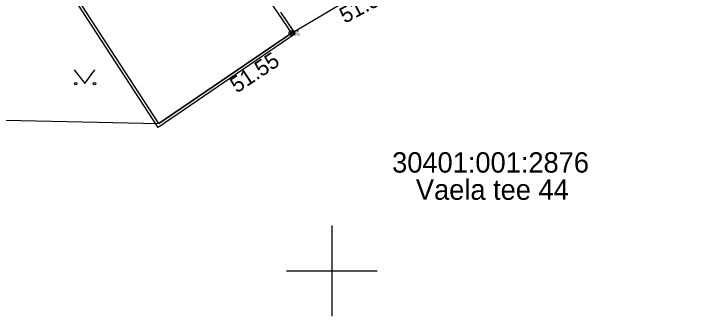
# Model space of a CAD drawing. Extents: x 543497 to 552146, y 6567125 to 6579845.
# Drawn here: x 546585.95 to 546616.77, y 6577748 to 6577761.34 of the extents above; entities that cross this region are included whole.
import ezdxf

# ---------------------------------------------------------------- set-up
doc = ezdxf.new("R2010")
doc.units = 0
for name, color, linetype in [('xref_Kangru tee 1_geodeesia$0$HALJASTUS', 7, 'Continuous'), ('xref_Kangru tee 1_geodeesia$0$HOONE', 7, 'Continuous'), ('xref_Kangru tee 1_geodeesia$0$HOONEDET', 7, 'Continuous'), ('xref_Kangru tee 1_geodeesia$0$korgus-EH2000', 7, 'Continuous'), ('xref_Kangru tee 1_geodeesia$0$mootkood', 7, 'Continuous'), ('xref_Kangru tee 1_geodeesia$0$MOOTKORG-eh2000', 7, 'Continuous'), ('xref_Kangru tee 1_geodeesia$0$mootmpunkt', 7, 'Continuous'), ('xref_Kangru tee 1_geodeesia$0$MOOTNR', 7, 'Continuous'), ('xref_Kangru tee 1_geodeesia$0$MOOTPIIR', 7, 'Continuous'), ('xref_Kangru tee 1_geodeesia$0$PIIR', 7, 'Continuous'), ('xref_Kangru tee 1_geodeesia$0$vork', 7, 'Continuous')]:
    doc.layers.add(name, color=color, linetype=linetype)

# ---------------------------------------------------------------- blocks, each defined once
blk = doc.blocks.new('xref_Kangru tee 1_geodeesia$0$MURU')
for p, q in [((-0.927, 1.213), (0, 0)), ((0, 0), (0.891, 1.213))]:
    blk.add_line(p, q)
for centre in [(-0.802, 0), (0.856, 0)]:
    blk.add_circle(centre, 0.11)
blk = doc.blocks.new('xref_Kangru tee 1_geodeesia$0$VKORIS')
for p, q in [((0, 4), (0, -4)), ((-4, 0), (4, 0))]:
    blk.add_line(p, q)

msp = doc.modelspace()

# ---------------------------------------------------------------- linework, layer by layer
at = {"layer": 'xref_Kangru tee 1_geodeesia$0$HOONE'}
msp.add_lwpolyline([(546592.359, 6577756.495), (546586.846, 6577764.962), (546589.527, 6577766.788), (546588.593, 6577768.16), (546591.611, 6577770.169), (546598.215, 6577760.492), (546592.359, 6577756.495)], dxfattribs=at)
at = {"layer": 'xref_Kangru tee 1_geodeesia$0$HOONEDET'}
for points in [[(546592.325, 6577756.324), (546586.678, 6577764.996), (546589.358, 6577766.82), (546588.423, 6577768.193), (546588.861, 6577768.485)], [(546597.73, 6577761.419), (546598.385, 6577760.46), (546592.325, 6577756.324)]]:
    msp.add_lwpolyline(points, dxfattribs=at)
at = {"layer": 'xref_Kangru tee 1_geodeesia$0$korgus-EH2000'}
msp.add_circle((546598.215, 6577760.492), 0.1, dxfattribs=at)
at = {"layer": 'xref_Kangru tee 1_geodeesia$0$mootmpunkt'}
msp.add_circle((546598.215, 6577760.492), 0.03, dxfattribs=at)
at = {"layer": 'xref_Kangru tee 1_geodeesia$0$MOOTPIIR'}
msp.add_lwpolyline([(546561.855, 6577757.167), (546592.359, 6577756.495), (546598.215, 6577760.492), (546601.677, 6577762.542), (546610.627, 6577767.104), (546615.752, 6577767.43), (546620.643, 6577768.598)], dxfattribs=at)

# ---------------------------------------------------------------- block references
at = {"layer": 'xref_Kangru tee 1_geodeesia$0$HALJASTUS', "xscale": 0.5, "yscale": 0.5}
msp.add_blockref('xref_Kangru tee 1_geodeesia$0$MURU', (546589.084, 6577758.261), dxfattribs=at)
at = {"layer": 'xref_Kangru tee 1_geodeesia$0$vork', "xscale": 0.5, "yscale": 0.5}
msp.add_blockref('xref_Kangru tee 1_geodeesia$0$VKORIS', (546600, 6577750), dxfattribs=at)

# ---------------------------------------------------------------- texts
at = {"layer": 'xref_Kangru tee 1_geodeesia$0$korgus-EH2000'}
for s, rotation, p in [(' 51.56 ', 27.8466, (546600.347, 6577760.779)), (' 51.55 ', 33.4516, (546595.584, 6577757.675))]:
    msp.add_text(s, height=0.7, rotation=rotation, dxfattribs=at).set_placement(p)
at = {"layer": 'xref_Kangru tee 1_geodeesia$0$mootkood'}
msp.add_text(' 9', height=0.1, dxfattribs=at).set_placement((546598.039, 6577760.525))
at = {"layer": 'xref_Kangru tee 1_geodeesia$0$MOOTKORG-eh2000'}
msp.add_text(' 51.55', height=0.1, dxfattribs=at).set_placement((546598.215, 6577760.392))
at = {"layer": 'xref_Kangru tee 1_geodeesia$0$MOOTNR'}
msp.add_text(' 1206', height=0.1, dxfattribs=at).set_placement((546598.215, 6577760.525))
at = {"layer": 'xref_Kangru tee 1_geodeesia$0$PIIR'}
for s, p in [('30401:001:2876', (546602.669, 6577754.331)), ('Vaela tee 44', (546603.719, 6577753.131))]:
    msp.add_text(s, height=0.9, dxfattribs=at).set_placement(p)

doc.saveas('drawing.dxf')
